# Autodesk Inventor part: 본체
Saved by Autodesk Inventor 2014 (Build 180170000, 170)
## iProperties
Created: 2026-04
Part Number: 본체
Material: 알루미늄 6061
Document SubType Name: Modeling
Designer: dg
Density: 2.71 g/cm^3
Appearance: 알루미늄 - 평지
Author: jhkim
Creation Date: 2026-03-27
Sending System: Autodesk Inventor 2026
Preprocessor: ST-DEVELOPER v20.1
Author: dg
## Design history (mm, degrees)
node "본체1"
node "솔리드1"
node "기준1"
